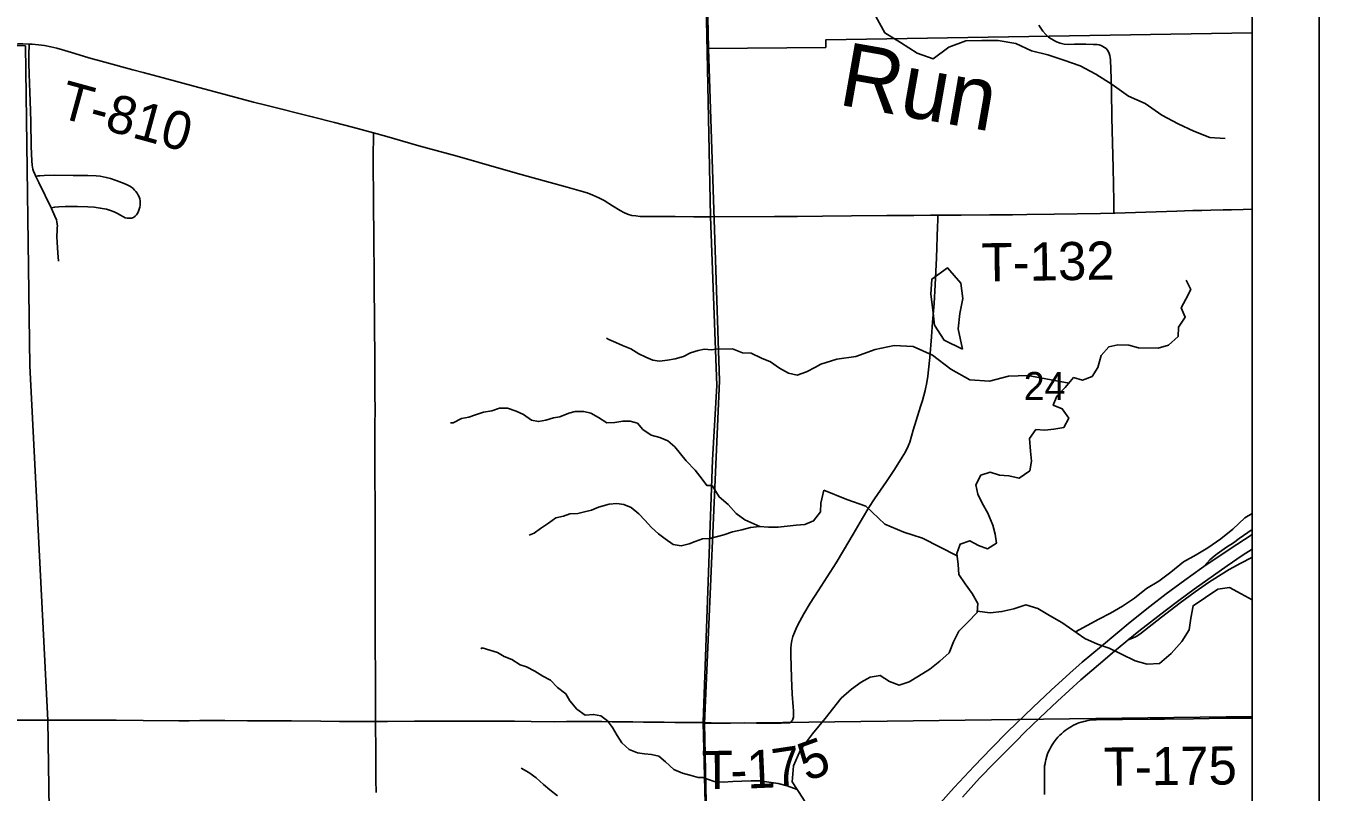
# Model space of a CAD drawing. Extents: x 0 to 34, y 0 to 22.
# Drawn here: x 7.072 to 9, y 18.776 to 19.918 of the extents above; entities that cross this region are included whole.
import ezdxf

# ---------------------------------------------------------------- set-up
doc = ezdxf.new("R2010")
doc.units = 0
for name, color, linetype in [('GM_X_Interchange_Ramps', 7, 'Continuous'), ('GM_X_Interstate_Route', 7, 'Continuous'), ('GM_X_Major_River', 7, 'Continuous'), ('GM_X_Minor_River', 7, 'Continuous'), ('GM_X_Minor_River_Text', 7, 'Continuous'), ('GM_X_Section', 7, 'Continuous'), ('GM_X_Section_Text', 7, 'Continuous'), ('GM_X_State_Shield', 7, 'Continuous'), ('GM_X_Township_Road', 7, 'Continuous'), ('GM_X_Township_Road_Text', 7, 'Continuous'), ('SH_Cut_Line', 7, 'Continuous'), ('SH_Data', 7, 'Continuous')]:
    doc.layers.add(name, color=color, linetype=linetype)

msp = doc.modelspace()

# ---------------------------------------------------------------- linework, layer by layer
at = {"layer": 'GM_X_Interchange_Ramps'}
for points in [[(8.9, 19.1672), (8.881, 19.1539), (8.8722, 19.1476), (8.8621, 19.1409), (8.8481, 19.1309), (8.8434, 19.1275), (8.8372, 19.1219), (8.8326, 19.117), (8.8283, 19.1119)], [(8.7153, 19.0026), (8.722, 19.0053), (8.7271, 19.0079), (8.7326, 19.0114), (8.7649, 19.0367), (8.7929, 19.0581), (8.8153, 19.0744), (8.835, 19.0883), (8.8498, 19.0977), (8.8658, 19.1074), (8.8832, 19.1171), (8.8995, 19.1257), (8.9, 19.1259)]]:
    msp.add_lwpolyline(points, dxfattribs=at)
at = {"layer": 'GM_X_Interstate_Route'}
for points in [[(8.1285, 16.8707), (8.1148, 17.8694), (8.0976, 18.2853), (8.0958, 18.3144), (8.0817, 18.88), (8.0959, 19.2713), (8.1023, 19.3817), (8.0929, 19.6339), (8.0678, 20.8562), (8.0675, 20.8733), (8.067, 20.8954), (8.0669, 20.9), (3.0331, 20.9), (3.0588, 19.9042), (3.067, 19.3838), (3.0747, 18.8969), (3.0724, 18.2926), (3.0939, 16.8719)], [(8.9, 16.8746), (8.9, 20.9), (8.0669, 20.9), (8.067, 20.8954), (8.0675, 20.8733), (8.0678, 20.8562), (8.0929, 19.6339), (8.1023, 19.3817), (8.0959, 19.2713), (8.0817, 18.88), (8.0958, 18.3144), (8.0976, 18.2853), (8.1148, 17.8694), (8.1285, 16.8707)], [(8.4353, 18.7596), (8.4561, 18.7827), (8.4859, 18.8144), (8.5117, 18.8413), (8.5357, 18.8655), (8.5736, 18.9024), (8.6007, 18.928), (8.6283, 18.953), (8.6469, 18.9694), (8.6754, 18.9934), (8.7185, 19.0291), (8.7476, 19.0524), (8.7721, 19.0714), (8.7996, 19.0917), (8.8249, 19.1096), (8.8283, 19.1119), (8.8661, 19.1375), (8.9, 19.1598)], [(8.4685, 18.7685), (8.4937, 18.7965), (8.5156, 18.8188), (8.5368, 18.8404), (8.5488, 18.8524), (8.5608, 18.8645), (8.5835, 18.8864), (8.6102, 18.9112), (8.645, 18.943), (8.6712, 18.9655), (8.695, 18.9859), (8.7121, 18.9999), (8.7153, 19.0026), (8.7314, 19.0158), (8.7485, 19.0291), (8.7704, 19.0462), (8.7909, 19.0615), (8.8138, 19.0785), (8.8627, 19.1133), (8.8852, 19.1283), (8.9, 19.138)]]:
    msp.add_lwpolyline(points, dxfattribs=at)
at = {"layer": 'GM_X_Major_River'}
for points in [[(8.8016, 19.5389), (8.8087, 19.5251), (8.8012, 19.5108), (8.7946, 19.4975), (8.8005, 19.4838), (8.7904, 19.4687), (8.7898, 19.455), (8.7755, 19.4419), (8.7599, 19.4375), (8.7306, 19.4379), (8.7166, 19.4419), (8.7002, 19.4425), (8.6865, 19.4397), (8.6753, 19.4265), (8.6701, 19.4087), (8.6615, 19.3955), (8.6474, 19.39), (8.6341, 19.3936), (8.6217, 19.3789), (8.609, 19.3658), (8.6038, 19.3525), (8.6171, 19.347), (8.6268, 19.3332), (8.6193, 19.3193), (8.6045, 19.3168), (8.5911, 19.3151), (8.5778, 19.3164), (8.5685, 19.3028), (8.5698, 19.2842), (8.5714, 19.2689), (8.569, 19.2549), (8.5528, 19.2437), (8.5377, 19.2473), (8.5236, 19.2483), (8.5096, 19.2527), (8.4958, 19.2483), (8.4884, 19.2339), (8.4912, 19.2198), (8.4979, 19.2064), (8.5064, 19.1915), (8.5138, 19.1739), (8.517, 19.1605), (8.5191, 19.1468), (8.5057, 19.1383), (8.4924, 19.1434), (8.4792, 19.1504), (8.4651, 19.1456), (8.4599, 19.1313), (8.462, 19.1149), (8.4629, 19.1), (8.4726, 19.0862), (8.483, 19.072), (8.4912, 19.0571), (8.4902, 19.0438), (8.4763, 19.0291), (8.4632, 19.0156), (8.455, 18.9998), (8.4487, 18.9835), (8.4348, 18.9711), (8.4198, 18.9592), (8.4029, 18.9487), (8.3887, 18.9402), (8.3742, 18.935), (8.3594, 18.9406), (8.3455, 18.9499), (8.331, 18.9474), (8.3172, 18.9396), (8.303, 18.9295), (8.2876, 18.9161), (8.2637, 18.8858)], [(8.2637, 18.8858), (8.2451, 18.8627), (8.2272, 18.8388), (8.2165, 18.8152), (8.2146, 18.7913), (8.2305, 18.7666), (8.2453, 18.7422), (8.2536, 18.7182), (8.2586, 18.6935), (8.246, 18.67), (8.2212, 18.6502), (8.2094, 18.6738), (8.2133, 18.6974), (8.1893, 18.7081), (8.1798, 18.6842), (8.1809, 18.6598), (8.1816, 18.6359), (8.1721, 18.6112), (8.1576, 18.5857), (8.1435, 18.5611), (8.1286, 18.5371), (8.1028, 18.511)]]:
    msp.add_lwpolyline(points, dxfattribs=at)
at = {"layer": 'GM_X_Minor_River'}
for points in [[(8.3394, 19.9318), (8.3528, 19.9073), (8.3762, 19.8933), (8.401, 19.8773), (8.4245, 19.869), (8.4483, 19.8862), (8.4732, 19.8954), (8.4972, 19.8962), (8.5215, 19.8963), (8.5477, 19.8917), (8.5715, 19.8808), (8.5957, 19.8747), (8.6196, 19.8668), (8.6438, 19.8581), (8.6672, 19.8457), (8.6917, 19.8305), (8.7158, 19.8131), (8.7408, 19.8021), (8.7656, 19.785), (8.7898, 19.7721), (8.8132, 19.7612), (8.837, 19.7517), (8.8597, 19.7498)], [(8.4685, 19.4359), (8.4409, 19.4494), (8.4268, 19.472), (8.4241, 19.4949), (8.4214, 19.5181), (8.4228, 19.5405), (8.4459, 19.5573), (8.4657, 19.5342), (8.4688, 19.5118), (8.4643, 19.489), (8.4621, 19.4662), (8.4685, 19.4359)], [(8.1012, 19.436), (8.0939, 19.4351), (8.0841, 19.436), (8.0746, 19.4342), (8.0632, 19.4305), (8.0525, 19.4253), (8.04, 19.4216), (8.0286, 19.4198), (8.0169, 19.418), (8.0071, 19.4197), (7.9965, 19.4239), (7.9859, 19.429), (7.9739, 19.4367), (7.9618, 19.4417), (7.9516, 19.446), (7.9411, 19.4506), (7.9377, 19.4526)], [(8.1012, 19.436), (8.1255, 19.4366), (8.1403, 19.4308), (8.1536, 19.4301), (8.1688, 19.4228), (8.1822, 19.4171), (8.1958, 19.4075), (8.2091, 19.4003), (8.2221, 19.3972), (8.2358, 19.4021), (8.2491, 19.4093), (8.2571, 19.4136)], [(8.2571, 19.4136), (8.2811, 19.4211), (8.3093, 19.4253), (8.3384, 19.4356), (8.3666, 19.4413), (8.3951, 19.4401), (8.4235, 19.4272), (8.4509, 19.4063), (8.4792, 19.3903), (8.5089, 19.3884), (8.5371, 19.396), (8.5657, 19.3968), (8.6273, 19.3856)], [(8.0953, 19.233), (8.0872, 19.233), (8.0805, 19.2425), (8.07, 19.2555), (8.0565, 19.2697), (8.0483, 19.28), (8.0396, 19.2904), (8.0291, 19.2992), (8.0174, 19.3046), (8.0042, 19.3078), (7.9922, 19.3162), (7.9839, 19.3258), (7.9733, 19.3286), (7.9623, 19.3287), (7.9502, 19.3265), (7.9385, 19.3262), (7.926, 19.334), (7.9147, 19.3405), (7.9042, 19.3429), (7.8913, 19.343), (7.8818, 19.3405), (7.8685, 19.3353), (7.859, 19.3335), (7.8476, 19.3302), (7.8366, 19.328), (7.826, 19.3304), (7.814, 19.3385), (7.8034, 19.3435), (7.7902, 19.3482), (7.7785, 19.3479), (7.7667, 19.3442), (7.7546, 19.3421), (7.7424, 19.338), (7.7325, 19.3347), (7.7215, 19.3325), (7.7094, 19.3262), (7.7052, 19.3262)], [(8.0919, 19.1537), (8.1125, 19.1591), (8.1258, 19.164), (8.1395, 19.1667), (8.1524, 19.17), (8.1661, 19.1719), (8.1795, 19.1708), (8.1935, 19.1707), (8.2072, 19.1722), (8.2205, 19.1737), (8.2335, 19.1748), (8.2464, 19.1801), (8.2567, 19.1938), (8.2575, 19.2067), (8.2615, 19.2258)], [(8.0953, 19.233), (8.1057, 19.2158), (8.119, 19.2043), (8.1312, 19.191), (8.1441, 19.1815), (8.1665, 19.1719)], [(8.2615, 19.2258), (8.296, 19.2122), (8.3244, 19.2019), (8.3529, 19.1753), (8.3809, 19.1631), (8.4089, 19.1544), (8.4604, 19.1278)], [(8.0919, 19.1537), (8.0809, 19.1534), (8.0702, 19.1493), (8.0608, 19.146), (8.049, 19.1431), (8.0373, 19.1447), (8.0252, 19.1532), (8.0151, 19.1609), (8.0049, 19.1704), (7.9948, 19.1812), (7.9858, 19.1907), (7.9745, 19.1999), (7.9636, 19.2046), (7.9533, 19.2058), (7.9416, 19.2048), (7.9257, 19.2004), (7.9154, 19.1963), (7.9048, 19.1934), (7.8953, 19.1912), (7.8832, 19.1906), (7.8737, 19.1873), (7.8623, 19.1847), (7.8512, 19.1769), (7.8394, 19.169), (7.8299, 19.1619), (7.8223, 19.1586)], [(8.6367, 19.0146), (8.6715, 19.0334), (8.6891, 19.0426), (8.7068, 19.053), (8.7248, 19.065), (8.7425, 19.0792), (8.7613, 19.0903), (8.779, 19.1038), (8.7979, 19.1191), (8.8167, 19.1295), (8.8343, 19.1399), (8.8535, 19.1534), (8.8712, 19.1676), (8.8894, 19.1848), (8.9, 19.1912)], [(8.4903, 19.0454), (8.5096, 19.0431), (8.5271, 19.0448), (8.5447, 19.0491), (8.5627, 19.055), (8.5805, 19.0494), (8.5982, 19.0393), (8.6163, 19.0288), (8.6509, 19.0047), (8.6695, 18.9965), (8.6869, 18.9902), (8.7054, 18.9816), (8.7258, 18.9714), (8.7436, 18.9666), (8.7619, 18.9675), (8.7796, 18.9825), (8.7954, 19.0002), (8.8063, 19.0175), (8.8089, 19.0353), (8.8122, 19.0535), (8.8306, 19.0658), (8.849, 19.0785), (8.8666, 19.081), (8.8839, 19.0712), (8.9, 19.0626)], [(8.0815, 18.7975), (8.0744, 18.7976), (8.0639, 18.8007), (8.051, 18.8039), (8.0382, 18.8097), (8.0258, 18.8212), (8.016, 18.8296), (8.0047, 18.832), (7.9945, 18.8329), (7.9842, 18.8345), (7.9718, 18.8396), (7.9605, 18.8495), (7.9538, 18.8602), (7.9467, 18.8721), (7.9392, 18.882), (7.9294, 18.8897), (7.9185, 18.8917), (7.906, 18.8907), (7.8935, 18.8995), (7.8831, 18.9121), (7.8771, 18.9221), (7.865, 18.932), (7.8542, 18.9428), (7.8429, 18.9489), (7.8312, 18.9563), (7.8187, 18.9625), (7.8089, 18.9656), (7.7965, 18.9733), (7.7855, 18.978), (7.7754, 18.9837), (7.764, 18.9873), (7.7523, 18.9908), (7.7504, 18.9893)], [(7.8648, 18.7704), (7.8535, 18.7793), (7.8437, 18.7873), (7.8332, 18.7973), (7.8219, 18.805), (7.8106, 18.8115)], [(8.0815, 18.7975), (8.0982, 18.7919), (8.1119, 18.7907), (8.1263, 18.7915), (8.1393, 18.7922), (8.1533, 18.7929), (8.1663, 18.7925), (8.1796, 18.7906), (8.1937, 18.7887), (8.207, 18.7852), (8.2221, 18.7797)]]:
    msp.add_lwpolyline(points, dxfattribs=at)
at = {"layer": 'GM_X_Section'}
for points in [[(7.0719, 19.8884), (7.0785, 19.4112), (7.105, 18.883), (6.0998, 18.8817), (6.0796, 19.8902)], [(7.105, 18.883), (7.1203, 17.8521), (6.1027, 17.8448), (6.0998, 18.8817)]]:
    msp.add_lwpolyline(points, close=True, dxfattribs=at)
at = {"layer": 'GM_X_State_Shield'}
for points in [[(8.9, 19.9075), (8.9, 20.9), (8.2605, 20.9), (8.2605, 20.8973), (8.0683, 20.8917), (8.0896, 19.8843), (8.2647, 19.8857), (8.2647, 19.8969)], [(8.9, 18.8885), (8.9, 19.9075), (8.2647, 19.8969), (8.2647, 19.8857), (8.0896, 19.8843), (8.1062, 19.3886), (8.0837, 18.878)], [(8.9, 17.8876), (8.9, 18.8885), (8.0837, 18.878), (8.1051, 17.868)]]:
    msp.add_lwpolyline(points, close=True, dxfattribs=at)
at = {"layer": 'GM_X_Township_Road'}
for points in [[(8.6941, 19.6388), (8.694, 19.6447), (8.6938, 19.6565), (8.6931, 19.7062), (8.6912, 19.7807), (8.6904, 19.8211), (8.69, 19.8397), (8.6895, 19.8531), (8.6889, 19.8674), (8.6885, 19.8708), (8.6878, 19.8736), (8.6871, 19.8765), (8.6861, 19.8793), (8.6846, 19.8818), (8.6827, 19.884), (8.6803, 19.8858), (8.6778, 19.8874), (8.6751, 19.8886), (8.6722, 19.8894), (8.6693, 19.8899), (8.6632, 19.8902), (8.6521, 19.8904), (8.6354, 19.8904), (8.6264, 19.8902), (8.6198, 19.8907), (8.6139, 19.892), (8.6085, 19.8939), (8.6004, 19.8984), (8.5965, 19.9012), (8.5924, 19.9051), (8.5884, 19.9098), (8.585, 19.9143), (8.5822, 19.9188)], [(7.0015, 19.8931), (7.0058, 19.8912), (7.0104, 19.89), (7.0145, 19.8893), (7.0203, 19.8891), (7.0313, 19.8897), (7.061, 19.891), (7.068, 19.8912), (7.0774, 19.8907)], [(7.0874, 19.6936), (7.0863, 19.6958), (7.0839, 19.7015), (7.0829, 19.7044), (7.0821, 19.7074), (7.0816, 19.7104), (7.0811, 19.7166), (7.0804, 19.7382), (7.0796, 19.7753), (7.0789, 19.8062), (7.0785, 19.8186), (7.0774, 19.8464), (7.0769, 19.8618), (7.0769, 19.8742), (7.0774, 19.8907)], [(7.0774, 19.8907), (7.0817, 19.8906), (7.091, 19.8898), (7.1003, 19.8886), (7.1094, 19.8869), (7.1185, 19.8847), (7.1304, 19.8811), (7.1452, 19.8765), (7.166, 19.8702), (7.1899, 19.8636), (7.2319, 19.8525), (7.247, 19.8486), (7.277, 19.8405), (7.3009, 19.8339), (7.3249, 19.8276), (7.373, 19.8148), (7.4119, 19.8043), (7.43, 19.7998), (7.4541, 19.7939), (7.4752, 19.7885), (7.4993, 19.7825), (7.5324, 19.774), (7.5594, 19.7669), (7.5906, 19.7584)], [(7.5935, 18.8811), (7.5934, 18.9088), (7.5933, 18.9305), (7.5933, 18.9554), (7.593, 18.9895), (7.5929, 19.0392), (7.5929, 19.1075), (7.5929, 19.1354), (7.5929, 19.1727), (7.593, 19.2037), (7.5927, 19.2472), (7.5927, 19.2751), (7.5926, 19.2999), (7.5927, 19.3186), (7.5928, 19.3496), (7.5927, 19.3651), (7.5927, 19.3931), (7.5925, 19.4303), (7.5921, 19.4644), (7.5919, 19.4893), (7.5917, 19.5203), (7.5915, 19.5389), (7.5914, 19.5576), (7.5912, 19.5886), (7.591, 19.6103), (7.5907, 19.6445), (7.5905, 19.6756), (7.5902, 19.6973), (7.5901, 19.7283), (7.5904, 19.7501), (7.5906, 19.7584)], [(7.5906, 19.7584), (7.6103, 19.7529), (7.6581, 19.7392), (7.715, 19.7235), (7.7479, 19.7143), (7.8017, 19.6989), (7.8284, 19.6914), (7.8792, 19.6776), (7.8967, 19.6727), (7.9089, 19.669), (7.9176, 19.6657), (7.9262, 19.6618), (7.9344, 19.6575), (7.9468, 19.6497), (7.958, 19.6428), (7.9634, 19.6397), (7.9691, 19.6374), (7.9755, 19.6354), (7.9814, 19.6346), (7.9878, 19.6339), (8.003, 19.6337), (8.0219, 19.6336), (8.0404, 19.6336), (8.0681, 19.6334), (8.0931, 19.6333)], [(7.1101, 19.6468), (7.1131, 19.6473), (7.1153, 19.6477), (7.1214, 19.6484), (7.1307, 19.6488), (7.1493, 19.6488), (7.1648, 19.6483), (7.1741, 19.6476), (7.1833, 19.6463), (7.1924, 19.6445), (7.1984, 19.6428), (7.2042, 19.6406), (7.2098, 19.638), (7.2125, 19.6364), (7.2178, 19.6333), (7.2206, 19.632), (7.2236, 19.6312), (7.2267, 19.6311), (7.2298, 19.6315), (7.2328, 19.6325), (7.2354, 19.6341), (7.2375, 19.6363), (7.2391, 19.639), (7.2404, 19.6418), (7.2413, 19.6448), (7.2421, 19.6478), (7.2426, 19.6509), (7.2429, 19.6539), (7.2428, 19.657), (7.2422, 19.6601), (7.2413, 19.663), (7.2399, 19.6658), (7.2383, 19.6685), (7.2364, 19.6709), (7.2343, 19.6732), (7.2321, 19.6754), (7.2297, 19.6773), (7.2271, 19.6791), (7.2244, 19.6806), (7.2188, 19.6832), (7.2072, 19.6876), (7.1983, 19.6905), (7.1923, 19.6921), (7.1832, 19.6937), (7.177, 19.6943), (7.1646, 19.6947), (7.1429, 19.6951), (7.115, 19.6953), (7.0995, 19.695), (7.0933, 19.6946), (7.0907, 19.6942), (7.0874, 19.6936)], [(7.1101, 19.6468), (7.1013, 19.6653), (7.0917, 19.6846), (7.0874, 19.6936)], [(7.1208, 19.567), (7.12, 19.5794), (7.1188, 19.5948), (7.1187, 19.6039), (7.1189, 19.6133), (7.1191, 19.6175), (7.1193, 19.62), (7.1191, 19.6226), (7.1186, 19.6256), (7.1178, 19.6286), (7.1156, 19.6344), (7.1107, 19.6457), (7.1101, 19.6468)], [(8.6941, 19.6388), (8.6954, 19.6388), (8.7879, 19.6418), (8.7993, 19.6422), (8.8117, 19.6426), (8.8251, 19.6429), (8.8385, 19.6432), (8.8571, 19.6436), (8.8694, 19.6438), (8.887, 19.6442), (8.9, 19.6445)], [(8.0931, 19.6333), (8.1882, 19.6336), (8.2224, 19.6338), (8.2596, 19.6344), (8.303, 19.6348), (8.3557, 19.6352), (8.396, 19.6354), (8.4208, 19.6358), (8.4317, 19.6356)], [(8.2132, 18.8805), (8.2143, 18.8819), (8.2151, 18.8833), (8.2157, 18.8846), (8.2164, 18.8876), (8.2167, 18.8907), (8.2166, 18.8938), (8.2163, 18.8969), (8.2159, 18.9031), (8.2146, 18.9216), (8.2134, 18.9464), (8.2124, 18.9804), (8.2125, 18.9897), (8.213, 18.9959), (8.214, 19.002), (8.2156, 19.008), (8.2178, 19.0138), (8.2215, 19.0223), (8.2258, 19.0306), (8.2319, 19.0414), (8.2416, 19.0573), (8.2531, 19.0757), (8.28, 19.1175), (8.2913, 19.136), (8.3053, 19.1602), (8.3192, 19.1844), (8.329, 19.2003), (8.3375, 19.2132), (8.3463, 19.226), (8.3551, 19.2388), (8.3671, 19.2568), (8.3787, 19.2751), (8.3833, 19.2832), (8.3874, 19.2915), (8.3897, 19.2973), (8.3925, 19.3062), (8.3951, 19.3151), (8.3996, 19.3299), (8.406, 19.3506), (8.4087, 19.3595), (8.4126, 19.3745), (8.4153, 19.3866), (8.4168, 19.3958), (8.418, 19.405), (8.4198, 19.4235), (8.4222, 19.4545), (8.4239, 19.4761), (8.426, 19.504), (8.4276, 19.5319), (8.4296, 19.5722), (8.4314, 19.6188), (8.4317, 19.628), (8.4317, 19.6356)], [(8.4317, 19.6356), (8.4467, 19.6358), (8.4664, 19.6359), (8.509, 19.6361), (8.543, 19.6364), (8.5645, 19.6366), (8.6049, 19.6372), (8.6739, 19.6384), (8.6941, 19.6388)], [(7.0206, 18.8838), (7.0859, 18.8833), (7.1294, 18.8833), (7.1512, 18.8831), (7.1853, 18.883), (7.2071, 18.8829), (7.2472, 18.8824), (7.3004, 18.8821), (7.316, 18.8823), (7.3315, 18.8824), (7.3532, 18.8824), (7.3688, 18.8824), (7.4029, 18.8822), (7.4216, 18.882), (7.4465, 18.8821), (7.4682, 18.8821), (7.5118, 18.8816), (7.5397, 18.8813), (7.5615, 18.881), (7.577, 18.8809), (7.5935, 18.8811)], [(7.5935, 18.8811), (7.5957, 18.8812), (7.6112, 18.8813), (7.6516, 18.8814), (7.6796, 18.8815), (7.7076, 18.8815), (7.7262, 18.8817), (7.7724, 18.8816), (7.8008, 18.8815), (7.8256, 18.8809), (7.8598, 18.8808), (7.8784, 18.881), (7.8908, 18.8811), (7.9124, 18.8811), (7.931, 18.8809), (7.9465, 18.8806), (7.9771, 18.8805), (7.9929, 18.88), (8.0052, 18.8802), (8.024, 18.88), (8.0396, 18.8798), (8.082, 18.8794)], [(7.5944, 18.7754), (7.5942, 18.794), (7.594, 18.8157), (7.5938, 18.8436), (7.5935, 18.8715), (7.5935, 18.8811)], [(8.082, 18.8794), (8.1061, 18.8787), (8.1215, 18.8788), (8.143, 18.8789), (8.1614, 18.8788), (8.1768, 18.8787), (8.1984, 18.8787), (8.2076, 18.8789), (8.2098, 18.8789), (8.2111, 18.8792), (8.2118, 18.8795), (8.2125, 18.88), (8.2132, 18.8805)], [(8.5908, 18.7724), (8.5905, 18.7872), (8.5905, 18.7941), (8.5905, 18.8033), (8.5906, 18.8084), (8.5907, 18.812), (8.5909, 18.815), (8.5914, 18.8185), (8.592, 18.8218), (8.5925, 18.8239), (8.5941, 18.8295), (8.5953, 18.833), (8.5968, 18.8365), (8.5979, 18.8389), (8.5999, 18.8428), (8.6022, 18.8465), (8.6052, 18.851), (8.608, 18.8548), (8.6107, 18.8577), (8.6137, 18.8609), (8.6158, 18.8629), (8.6188, 18.8656), (8.6214, 18.8677), (8.6242, 18.8697), (8.6273, 18.8718), (8.6307, 18.8738), (8.6339, 18.8755), (8.6373, 18.8771), (8.6394, 18.878)], [(8.6394, 18.878), (8.642, 18.8789), (8.6452, 18.8802), (8.6477, 18.8807), (8.6495, 18.8812), (8.6518, 18.8817), (8.6552, 18.8824), (8.6583, 18.8829), (8.6636, 18.8835), (8.6676, 18.8838), (8.6727, 18.8839), (8.7069, 18.8841), (8.7481, 18.8846), (8.7695, 18.8847), (8.8127, 18.8852), (8.8592, 18.8859), (8.8913, 18.8862), (8.9, 18.8862)]]:
    msp.add_lwpolyline(points, dxfattribs=at)
at = {"layer": 'SH_Cut_Line'}
for points in [[(8.1285, 16.8707), (8.1148, 17.8694), (8.0976, 18.2853), (8.0958, 18.3144), (8.0817, 18.88), (8.0959, 19.2713), (8.1023, 19.3817), (8.0929, 19.6339), (8.0678, 20.8562), (8.0675, 20.8733), (8.067, 20.8954), (8.0669, 20.9), (2.1, 20.9), (2.1, 14.1)], [(8.9, 14.1), (8.9, 20.9), (8.0669, 20.9), (8.067, 20.8954), (8.0675, 20.8733), (8.0678, 20.8562), (8.0929, 19.6339), (8.1023, 19.3817), (8.0959, 19.2713), (8.0817, 18.88), (8.0958, 18.3144), (8.0976, 18.2853), (8.1148, 17.8694), (8.1285, 16.8707)]]:
    msp.add_lwpolyline(points, dxfattribs=at)
at = {"layer": 'SH_Data'}
for p, q in [((9, 21), (9, 14)), ((8.9, 20.9), (8.9, 14.1))]:
    msp.add_line(p, q, dxfattribs=at)

# ---------------------------------------------------------------- texts
at = {"layer": 'GM_X_Minor_River_Text'}
msp.add_text('Run', height=0.09473, rotation=349.992, dxfattribs=at).set_placement((8.2814, 19.8008))
at = {"layer": 'GM_X_Section_Text'}
msp.add_text('24', height=0.04186, rotation=0, dxfattribs=at).set_placement((8.5597, 19.3602))
at = {"layer": 'GM_X_Township_Road_Text'}
for s, height, rotation, p in [('T-810', 0.05682, 344.6716, (7.119, 19.7822)), ('T-132', 0.05682, 0.8425, (8.4972, 19.537)), ('5', 0.0568, 19.9134, (8.236, 18.7914)), ('T', 0.0568, 0.4029, (8.0799, 18.7804)), ('1', 0.0568, 2.5273, (8.148, 18.7811)), ('7', 0.0568, 8.5053, (8.1894, 18.7832)), ('T-175', 0.05682, 0.5605, (8.6791, 18.7854)), ('-', 0.0568, 0.8355, (8.1229, 18.7807))]:
    msp.add_text(s, height=height, rotation=rotation, dxfattribs=at).set_placement(p)

doc.saveas('drawing.dxf')
